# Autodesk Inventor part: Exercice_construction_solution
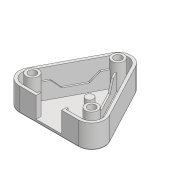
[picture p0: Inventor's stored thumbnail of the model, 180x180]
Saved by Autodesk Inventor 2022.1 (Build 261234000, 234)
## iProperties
Created: 2018-06
Part Number: Exercice_construction_solution
Material: Générique
Document SubType Name: Modeling
Designer: Fabian Perrée
Density: 1 g/cm^3
Appearance: Par défaut
Mass: 7.75757 g
Surface Area: 99.8659 cm^2
Volume: 7.75757 cm^3
Author: Fabian Perrée
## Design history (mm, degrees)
node "Annotations"
  node "Cote linéaire 1" dims "d55" = 8 (derived)
  node "Cote angulaire 1" dims "d58" = 45 deg (derived)
  node "Cote linéaire 2" dims "d61" = 10 (derived)
  node "Cote linéaire 3" dims "d63" = 5 (derived)
  node "Cote linéaire 4" dims "d66" = 1 (derived)
sketch "Esquisse1"
  geometry: L1 (0, 0)-(0, -59.098); L2 (0, 0)-(7.75, 0); L3 (25.07, -11.743)-(7.07, -45.743); L4 (-7.07, -45.743)-(-25.07, -11.743); L5 (-18, 0)-(-7.75, 0); L6 (14.25, -19.25)-(11, -19.25); L7 (9, -21.25)-(14.25, -21.25); L8 (14.25, -21.25)-(14.25, -19.25); L9 (11, -19.25)-(11, -16); L10 (11, -16)-(9, -16); L11 (9, -16)-(9, -21.25); L12 (-23.524, -10.924)-(-5.524, -44.924); L13 (5.524, -44.924)-(23.524, -10.924); L14 (7.75, 0)-(7.75, -3); L15 (7.75, -3)-(8.75, -3); L16 (8.75, -3)-(8.75, -1.75); L17 (-7.75, -3)-(-8.75, -3); L18 (-8.75, -3)-(-8.75, -1.75); L19 (-7.75, 0)-(-7.75, -3); L20 (18, -1.75)-(8.75, -1.75); L21 (-8.75, -1.75)-(-18, -1.75); L22 (7.75, 0)-(18, 0); L23 (-7.75, 0)-(0, 0); C1 r 2.375 at (18, -8); C2 r 2.375 at (-18, -8); C3 r 2.375 at (0, -42); C4 r 3.75 at (18, -8); C5 r 3.75 at (0, -42); C6 r 3.75 at (-18, -8); C7 r 2.375 at (0, -24.75); A1 r 8 centre (18, -8) between (25.07, -11.743) and (18, 0); A2 r 8 centre (0, -42) between (-7.07, -45.743) and (7.07, -45.743); A3 r 8 centre (-18, -8) between (-18, 0) and (-25.07, -11.743); A4 r 6.25 centre (-18, -8) between (-18, -1.75) and (-23.524, -10.924); A5 r 6.25 centre (0, -42) between (-5.524, -44.924) and (5.524, -44.924); A6 r 6.25 centre (18, -8) between (23.524, -10.924) and (18, -1.75); 1 further point
  constraints: 46 end point, 13 centre point, 12 point on circle, 10 tangent, 8 perpendicular, 7 point on line, 6 equal radius, 4 horizontal, 4 symmetric about line, 3 coincident, 3 vertical, 2 concentric, 1 parallel, 6 other
  dimensions: "d0" = 34 vertical distance of C3.centre C1.centre; "d1" = 2 distance of L7.end L6.start; "d2" = 3.25 distance of L6.end L9.end; "d3" = 9 distance between parallel lines of L1 L11; "d4" = 13.25 distance from line of C1.centre L7; "d5" = 8 radius of A1; "d6" = 7.5 diameter of C4; "d7" = 36 distance of C2.centre C1.centre; "d8" = 4.75 diameter of C1; "d9" = 4.75 diameter of C7; "d10" = 16.75 vertical distance of C1.centre C7.centre; "d11" = 1.75 radial gap between concentric circles of A1 A6; "d12" = 1 distance of L14.end L15.end; "d13" = 15.5 diameter of L14 L1; "d14" = 3 distance of L2.end L14.end; "d41" = 5.25 distance of L10.end L7.start
extrude "Extrusion1" new body sketch "Esquisse1" distance "d15" = 1.75; taper "d16" = 0 deg
extrude "Extrusion2" join sketch "Esquisse1" distance "d17" = 12.5; taper "d18" = 0 deg
extrude "Extrusion3" join sketch "Esquisse1" distance "d19" = 15.25; taper "d20" = 0 deg
extrude "Extrusion4" join sketch "Esquisse1" distance "d21" = 3.25; taper "d22" = 0 deg
node "Plan de construction1"
fillet "Congé1" dims "d40" = 0.5
node "Plan de construction2"
  node "Axe de construction1"
  node "Axe de construction2"
sketch "Esquisse3"
  geometry: L1 (10, 36.096)-(10, 30.471); L2 (10, 30.471)-(5, 25.471); L3 (5, 25.471)-(5, 13); L4 (5, 13)-(10, 8); L5 (10, 8)-(10, 2.375); L6 (15.25, 34.721)-(15.25, 42.221) reference; L7 (15.25, 3.75)-(15.25, 34.721); L8 (15.25, 19.235)-(0, 19.235); L9 (15.25, 2.375)-(-1.75, 2.375) reference; L10 (15.25, 36.096)-(-1.75, 36.096) reference; L11 (0, 34.721)-(15.25, 34.721) reference; L12 (15.25, 2.375)-(-1.75, 2.375) reference; L13 (0, 2.375)-(0, 36.096); L14 (0, 38.471)-(0, 0) reference; L15 (15.25, 38.471)-(0, 38.471); 3 further points
  constraints: 18 end point, 5 point on line, 3 midpoint, 2 vertical, 1 collinear, 1 horizontal, 1 parallel, 2 other
  dimensions: "d45" = 135 deg angle of L1 L2; "d50" = 8 distance from line of L1.end L15; "d51" = 10 distance between parallel lines of L13 L1; "d52" = 5 distance between parallel lines of L13 L3
extrude "Extrusion5" join sketch "Esquisse3" stored distance "d47" = 1; taper "d48" = 0 deg
mirror "Symétrie2"
node "Solide1"
other parameters: "d23" = 3.25, "d53" = -14.22576 (derived), "d54" = 4.68695 (derived), "d56" = 5.63918 (derived), "d57" = 1.86161 (derived), "d59" = 0 (derived), "d62" = 2.28379 (derived), "d64" = 0 (derived)
